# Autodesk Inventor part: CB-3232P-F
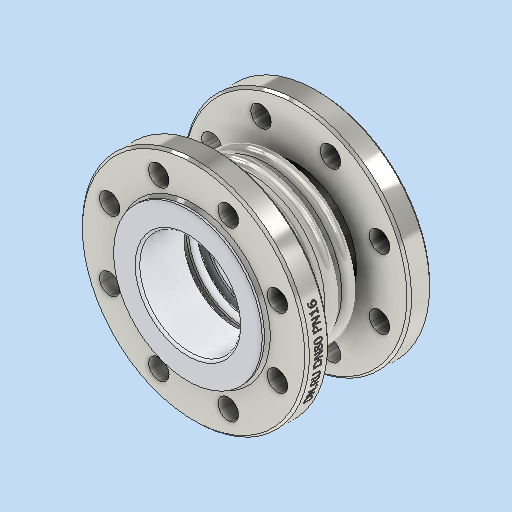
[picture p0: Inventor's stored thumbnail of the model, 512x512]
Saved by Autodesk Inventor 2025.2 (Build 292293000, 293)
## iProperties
Company: DN.RU
Created: 2026-04
Part Number: CB-3232P-F
Material: Типовые
Document SubType Name: Modeling
Designer: DN.RU
Density: 6.09172 g/cm^3
Appearance: По умолчанию
Description: D140-02140
Mass: 6900 g
Surface Area: 2884.98 cm^2
Volume: 1132.69 cm^3
Author: DN.RU
Title: Компенсатор сильфонный осевой DN.ru Ду80 Ру16
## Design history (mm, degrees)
sketch "Эскиз1"
  geometry: L1 (0, 0)-(0, -55); L2 (50.5, -55)-(50.5, 0); L3 (50.5, 0)-(0, 0); L4 (50.5, 0)-(50.5, 0); L5 (35.5, 0)-(65.5, 0); L6 (35.5, -5)-(65.5, -5); L7 (65.5, 5)-(35.5, 5); L8 (65.5, -3)-(35.5, -3); L9 (35.5, 3)-(65.5, 3); L10 (65.5, -10)-(35.5, -10); L11 (35.5, -12)-(65.5, -12); L12 (35.5, -15)-(65.5, -15); L13 (35.5, -20)-(65.5, -20); L14 (65.5, -18)-(35.5, -18); L15 (0, -55)-(50.5, -55); L16 (50.5, -55)-(44.5, -55); L17 (44.5, -55)-(44.5, -18); L18 (50.5, -12)-(48.5, -12); L19 (48.5, -12)-(48.5, -3); L20 (50.5, 3)-(48.5, 3); L21 (48.5, 3)-(48.5, 0); L22 (0, -55)-(0, -35); L23 (0, -35)-(100, -35); L24 (100, -35)-(100, -55); L25 (100, -55)-(0, -55); L26 (50.5, -35)-(50.5, -45); L27 (50.5, -45)-(53.5, -45); L28 (53.5, -45)-(53.5, -35); L29 (53.5, -35)-(50.5, -35); L30 (50.5, 0)-(70.5, 0); A1 r 5 centre (35.5, 0) between (35.5, 5) and (35.5, -5); A2 r 5 centre (65.5, 0) between (65.5, -5) and (65.5, 5); A3 r 3 centre (35.5, 0) between (35.5, 3) and (35.5, -3); A4 r 3 centre (65.5, 0) between (65.5, -3) and (65.5, 3); A5 r 3 centre (35.5, -15) between (35.5, -12) and (35.5, -18); A6 r 5 centre (35.5, -15) between (35.5, -10) and (35.5, -20); A7 r 3 centre (65.5, -15) between (65.5, -18) and (65.5, -12); A8 r 5 centre (65.5, -15) between (65.5, -20) and (65.5, -10); 19 further points
  constraints: 64 end point, 17 point on circle, 14 point on line, 8 centre point, 7 parallel, 5 perpendicular, 4 tangent, 3 midpoint, 2 vertical, 1 horizontal, 25 other
  dimensions: "d0" = 55 distance of L1.start L1.end; "d3" = 0 distance of L2.end L4.end; "d4" = 15 distance of L4.end L5.end; "d5" = 10 diameter of A2; "d6" = 2 distance between parallel lines of L6 L8; "d9" = 15 distance of L4.end point (50.5, -15); "d18" = 2 distance of L18.start L18.end; "d19" = 2 distance of L20.start L20.end; "d27" = 44.5 distance between parallel lines of L1 L17; "d28" = 6 distance between parallel lines of L2 L17; "d29" = 20 distance of L1.end L22.end; "d30" = 100 distance of L22.end L23.end; "d31" = 10 distance of L26.start L26.end; "d32" = 3 distance of L27.end L26.end
revolve "Вращение1" sketch "Эскиз1" stored, may be unused: angle "d20" = 360 deg
sketch "Эскиз3" dims "d33" = 160
  geometry: L1 (0, 0)-(71.096, 29.449); L2 (0, 0)-(76.954, 0); C1 r 9 at (73.91, 30.615); C2 r 9 at (30.615, 73.91); C3 r 9 at (-30.615, 73.91); C4 r 9 at (-73.91, 30.615); C5 r 44.5 at (0, 0) reference; C6 r 67.5 at (0, 0); C7 r 100 at (0, 0) reference; C8 r 9 at (-73.91, -30.615); C9 r 9 at (-30.615, -73.91); C10 r 9 at (30.615, -73.91); C11 r 9 at (73.91, -30.615); 1 further point
  constraints: 9 centre point, 4 end point, 2 coincident, 1 equal length, 1 horizontal, 1 point on line, 20 other
  dimensions: "d34" = 22.5 deg angle of L2 L1; "d35" = 18 diameter of C1; "d38" = 360 deg dimension on point (0, 0) C1.centre (derived); "d40" = 135 diameter of C6
  node "Эскиз — круговой массив1" dims "d38" = 360 deg (derived)
extrude "Выдавливание1" cut sketch "Эскиз3" stored distance "d41" = 10; taper "d42" = 0 deg
extrude "Выдавливание2" join sketch "Эскиз3" distance "d43" = 3; taper "d44" = 0 deg
chamfer "Фаска2" distance "d45" = 3; stored, may be unused: second distance "d46" = 2, angle "d47" = 45 deg
chamfer "Фаска3" distance "d48" = 2; stored, may be unused: second distance "d49" = 2, angle "d50" = 45 deg
mirror "Зеркальное отражение2"
fillet "Сопряжение2" dims "d51" = 1
node "РабПлоскость2"
sketch "Эскиз4"
  geometry: L1 (-44.383, 3.589)-(46.395, 3.589); L2 (46.395, 3.589)-(46.395, 0.413); L3 (46.395, 0.413)-(-44.383, 0.413); L4 (-44.383, 0.413)-(-44.383, 3.589); 1 further point
  constraints: 2 other
feature "Рельеф2" sketch "Эскиз4" dims "d3" = 0, "d52" = 0.1, "d53" = 0
sketch "Эскиз5"
  geometry: C1 r 44.5 at (0, 0) reference; C2 r 65.5 at (0, 0); 1 further point
  constraints: 1 centre point
  dimensions: "d54" = 21 radial gap between concentric circles of C1 C2
extrude "Выдавливание3" join sketch "Эскиз5" distance "d55" = 2; taper "d56" = 0 deg
fillet "Сопряжение3" dims "d57" = 2
mirror "Зеркальное отражение3"
node "Твердое тело1"
node "Эскиз — прямоугольный массив1" dims "d9" = 15, "d12" = 10
